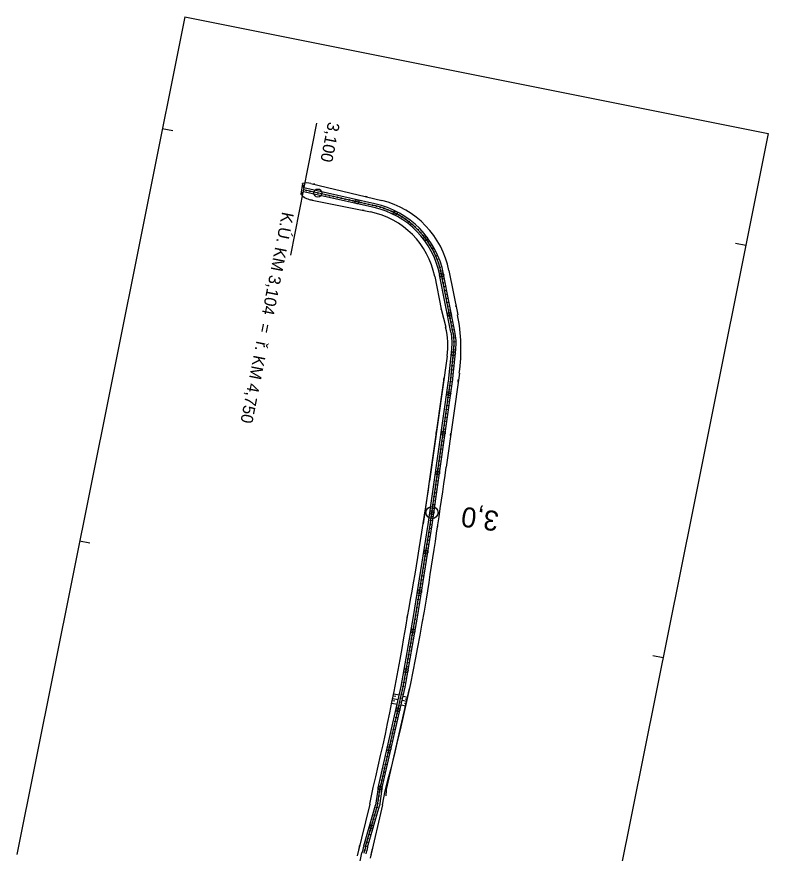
# Model space of a CAD drawing. Extents: x -548552 to -543113, y -1131925 to -1123599.
# Drawn here: x -548501.2 to -548313.7, y -1124330.1 to -1124121.2 of the extents above; entities that cross this region are included whole.
import ezdxf

# ---------------------------------------------------------------- set-up
doc = ezdxf.new("R2010")
doc.units = 0
for name, color, linetype in [('HRANY', 7, 'Continuous'), ('Profile', 7, 'Continuous'), ('PROFILY NÁVRH', 7, 'Continuous'), ('STANIČENÍ', 7, 'Continuous'), ('SVAHY', 7, 'Continuous')]:
    doc.layers.add(name, color=color, linetype=linetype)

msp = doc.modelspace()

# ---------------------------------------------------------------- linework, layer by layer
at = {"layer": 'HRANY'}
for p, q in [((-548394.66, -1124211.53), (-548399.79, -1124247.8)), ((-548413.11, -1124317.81), (-548412.26, -1124313.64)), ((-548409.92, -1124318), (-548409.29, -1124314.45))]:
    msp.add_line(p, q, dxfattribs=at)
msp.add_lwpolyline([(-548409.01, -1124315.73), (-548408.93, -1124314.27), (-548408.93, -1124314.11), (-548403.18, -1124288.88)], dxfattribs=at)
at = {"layer": 'Profile'}
for p, q in [((-548459.29, -1124121.17), (-548478.12, -1124215.1)), ((-548459.29, -1124121.17), (-548313.69, -1124150.35)), ((-548462.31, -1124149.67), (-548464.9, -1124149.15)), ((-548313.69, -1124150.35), (-548332.52, -1124244.29)), ((-548319.3, -1124178.33), (-548321.89, -1124177.81)), ((-548478.12, -1124215.1), (-548501.23, -1124330.39)), ((-548332.52, -1124244.29), (-548355.63, -1124359.57)), ((-548482.95, -1124252.62), (-548485.54, -1124252.1)), ((-548339.93, -1124281.29), (-548342.52, -1124280.77))]:
    msp.add_line(p, q, dxfattribs=at)
at = {"layer": 'PROFILY NÁVRH'}
for p, q in [((-548429.93, -1124162.84), (-548430.3, -1124165.5)), ((-548429.56, -1124163.91), (-548429.93, -1124162.84)), ((-548427.8, -1124162.78), (-548410.15, -1124167.05)), ((-548426.87, -1124163), (-548427.15, -1124162.94)), ((-548429.67, -1124164.91), (-548430.3, -1124165.5)), ((-548412.06, -1124168.83), (-548429.67, -1124164.91)), ((-548411.95, -1124168.35), (-548429.62, -1124164.41)), ((-548411.84, -1124167.86), (-548429.56, -1124163.91)), ((-548427.94, -1124166.87), (-548412.97, -1124169.91)), ((-548427.42, -1124166.98), (-548427.85, -1124166.88)), ((-548413.81, -1124166.16), (-548414.22, -1124166.07)), ((-548414.55, -1124169.59), (-548414.96, -1124169.5)), ((-548396.91, -1124186.06), (-548395.31, -1124194.21)), ((-548392.86, -1124199.93), (-548395.69, -1124185.62)), ((-548391.88, -1124199.74), (-548394.71, -1124185.42)), ((-548393.37, -1124184.56), (-548391.19, -1124195.59)), ((-548395.31, -1124194.21), (-548394.19, -1124198.68)), ((-548393.39, -1124211.43), (-548392.66, -1124204.2)), ((-548392.39, -1124211.53), (-548391.67, -1124204.29)), ((-548393.82, -1124205.97), (-548398.22, -1124237.17)), ((-548390.78, -1124210.15), (-548394.06, -1124233.66)), ((-548398.53, -1124247.94), (-548393.46, -1124212.09)), ((-548397.54, -1124248.09), (-548392.47, -1124212.23)), ((-548402.21, -1124270.91), (-548398.53, -1124247.94)), ((-548401.23, -1124271.07), (-548397.54, -1124248.09)), ((-548396.23, -1124248.66), (-548396.18, -1124248.35)), ((-548405.29, -1124288.38), (-548402.21, -1124270.91)), ((-548404.31, -1124288.58), (-548401.23, -1124271.07)), ((-548411.06, -1124313.75), (-548405.29, -1124288.38)), ((-548410.08, -1124313.97), (-548404.31, -1124288.58)), ((-548411.06, -1124313.75), (-548411.73, -1124318.04)), ((-548410.08, -1124313.97), (-548410.72, -1124318.18)), ((-548413.11, -1124317.81), (-548416.3, -1124330.72)), ((-548414.64, -1124328.25), (-548411.73, -1124318.04)), ((-548413.68, -1124328.52), (-548410.72, -1124318.18)), ((-548409.92, -1124318), (-548413.06, -1124331.3)), ((-548421.59, -1124360.69), (-548415.07, -1124329.96))]:
    msp.add_line(p, q, dxfattribs=at)
for centre, radius, start, end in [((-548428.76, -1124166.75), 4.08, 76.4037, 106.7435), ((-548427.09, -1124162.67), 4.28, 221.3954, 258.5091), ((-548415.43, -1124188.91), 22.49, 11.1558, 76.4037), ((-548417.07, -1124190.04), 20.54, 11.1558, 78.5091), ((-548434.29, -1124204.08), 43.92, 352.057, 11.1558), ((-548412.74, -1124203.3), 19.11, 351.9688, 13.9759), ((-549961.12, -1124015.02), 1582.24, 350.85166, 352.05699), ((-549178.83, -1124127.03), 788.35, 349.48348, 351.9688), ((-548865.33, -1124191.48), 472.33, 344.9096, 350.8517), ((-548972.72, -1124179.46), 576.3, 346.53607, 350.86921)]:
    msp.add_arc(centre, radius, start, end, dxfattribs=at)
for centre, major_axis, ratio, start_param, end_param in [((-548416.73, -1124189.76), (20.15, 7.35), 0.999974, 6.128055, 7.284874), ((-548416.73, -1124189.76), (21.08, 7.69), 0.999975, 6.128055, 7.284874), ((-548407.05, -1124202.74), (-1.33, 14.44), 0.997522, 4.519884, 4.815157), ((-548407.05, -1124202.74), (-1.43, 15.43), 0.997682, 4.519884, 4.815157), ((-548406.13, -1124210.24), (1.81, 14.39), 0.88281, 4.695435, 4.741018), ((-548406.13, -1124210.24), (1.94, 15.38), 0.890371, 4.695435, 4.741018), ((-548390.14, -1124335.25), (-10.13, -23.4), 0.999371, 4.842823, 4.912092), ((-548390.14, -1124335.25), (-9.74, -22.48), 0.999345, 4.842826, 4.912097)]:
    msp.add_ellipse(centre, major_axis=major_axis, ratio=ratio, start_param=start_param, end_param=end_param, dxfattribs=at)
at = {"layer": 'STANIČENÍ'}
for p, q in [((-548432.86, -1124180.71), (-548426.31, -1124147.71)), ((-548392.37, -1124199.84), (-548395.2, -1124185.52)), ((-548395.29, -1124194.3), (-548395.33, -1124194.1)), ((-548391.59, -1124193.58), (-548391.63, -1124193.39)), ((-548392.89, -1124211.48), (-548392.16, -1124204.24)), ((-548398.03, -1124248.01), (-548392.97, -1124212.16)), ((-548396.54, -1124225.25), (-548396.45, -1124224.61)), ((-548392.96, -1124225.76), (-548392.87, -1124225.14)), ((-548401.72, -1124270.99), (-548398.03, -1124248.01)), ((-548399.79, -1124247.77), (-548399.74, -1124247.43)), ((-548404.8, -1124288.48), (-548401.72, -1124270.99)), ((-548403.78, -1124271.21), (-548403.68, -1124270.65)), ((-548399.89, -1124271.96), (-548399.78, -1124271.33)), ((-548410.57, -1124313.86), (-548404.8, -1124288.48)), ((-548406.9, -1124288.78), (-548406.77, -1124288.24)), ((-548403.3, -1124289.56), (-548403.2, -1124289.12)), ((-548410.85, -1124315.88), (-548410.57, -1124313.86)), ((-548411.23, -1124318.12), (-548410.85, -1124315.88)), ((-548414.16, -1124328.39), (-548411.23, -1124318.12))]:
    msp.add_line(p, q, dxfattribs=at)
for centre, radius in [((-548428.93, -1124164.56), 0.1), ((-548428, -1124164.77), 0.1), ((-548427.07, -1124164.98), 0.1), ((-548426.09, -1124165.19), 1), ((-548426.1, -1124165.19), 0.1), ((-548425.12, -1124165.41), 0.1), ((-548424.14, -1124165.63), 0.1), ((-548423.17, -1124165.84), 0.1), ((-548422.19, -1124166.06), 0.1), ((-548421.21, -1124166.28), 0.1), ((-548420.24, -1124166.49), 0.1), ((-548419.26, -1124166.71), 0.1), ((-548418.28, -1124166.92), 0.1), ((-548417.31, -1124167.14), 0.1), ((-548416.33, -1124167.36), 0.5), ((-548416.33, -1124167.36), 0.1), ((-548415.36, -1124167.57), 0.1), ((-548414.38, -1124167.79), 0.1), ((-548413.4, -1124168.01), 0.1), ((-548412.43, -1124168.22), 0.1), ((-548411.46, -1124168.46), 0.1), ((-548410.49, -1124168.72), 0.1), ((-548409.54, -1124169.03), 0.1), ((-548408.6, -1124169.38), 0.1), ((-548407.68, -1124169.77), 0.1), ((-548406.78, -1124170.2), 0.5), ((-548406.78, -1124170.2), 0.1), ((-548405.9, -1124170.68), 0.1), ((-548405.04, -1124171.19), 0.1), ((-548404.21, -1124171.74), 0.1), ((-548403.4, -1124172.33), 0.1), ((-548402.62, -1124172.96), 0.1), ((-548401.87, -1124173.62), 0.1), ((-548401.15, -1124174.31), 0.1), ((-548400.46, -1124175.03), 0.1), ((-548399.81, -1124175.79), 0.1), ((-548399.19, -1124176.58), 0.5), ((-548399.19, -1124176.58), 0.1), ((-548398.6, -1124177.39), 0.1), ((-548398.06, -1124178.23), 0.1), ((-548397.55, -1124179.09), 0.1), ((-548397.09, -1124179.97), 0.1), ((-548396.66, -1124180.88), 0.1), ((-548396.28, -1124181.8), 0.1), ((-548395.94, -1124182.74), 0.1), ((-548395.64, -1124183.7), 0.1), ((-548395.17, -1124185.64), 0.5), ((-548395.38, -1124184.66), 0.1), ((-548395.17, -1124185.64), 0.1), ((-548394.98, -1124186.62), 0.1), ((-548394.79, -1124187.6), 0.1), ((-548394.59, -1124188.58), 0.1), ((-548394.4, -1124189.56), 0.1), ((-548394.2, -1124190.55), 0.1), ((-548394.01, -1124191.53), 0.1), ((-548393.82, -1124192.51), 0.1), ((-548393.62, -1124193.49), 0.1), ((-548393.43, -1124194.47), 0.1), ((-548393.24, -1124195.45), 0.5), ((-548393.24, -1124195.45), 0.1), ((-548393.04, -1124196.43), 0.1), ((-548392.85, -1124197.41), 0.1), ((-548392.66, -1124198.39), 0.1), ((-548392.46, -1124199.38), 0.1), ((-548392.28, -1124200.36), 0.1), ((-548392.15, -1124201.35), 0.1), ((-548392.09, -1124202.35), 0.1), ((-548392.27, -1124205.34), 0.5), ((-548392.17, -1124204.34), 0.1), ((-548392.1, -1124203.35), 0.1), ((-548392.37, -1124206.33), 0.1), ((-548392.27, -1124205.34), 0.1), ((-548392.67, -1124209.32), 0.1), ((-548392.57, -1124208.32), 0.1), ((-548392.47, -1124207.33), 0.1), ((-548392.87, -1124211.31), 0.1), ((-548392.77, -1124210.31), 0.1), ((-548393.13, -1124213.29), 0.1), ((-548392.99, -1124212.3), 0.1), ((-548393.41, -1124215.27), 0.5), ((-548393.41, -1124215.27), 0.1), ((-548393.27, -1124214.28), 0.1), ((-548393.69, -1124217.25), 0.1), ((-548393.55, -1124216.26), 0.1), ((-548393.97, -1124219.23), 0.1), ((-548393.83, -1124218.24), 0.1), ((-548394.25, -1124221.21), 0.1), ((-548394.11, -1124220.22), 0.1), ((-548394.53, -1124223.19), 0.1), ((-548394.39, -1124222.2), 0.1), ((-548394.81, -1124225.17), 0.5), ((-548394.81, -1124225.17), 0.1), ((-548394.67, -1124224.18), 0.1), ((-548395.09, -1124227.15), 0.1), ((-548394.95, -1124226.16), 0.1), ((-548395.51, -1124230.12), 0.1), ((-548395.37, -1124229.13), 0.1), ((-548395.23, -1124228.14), 0.1), ((-548395.79, -1124232.1), 0.1), ((-548395.65, -1124231.11), 0.1), ((-548396.07, -1124234.09), 0.1), ((-548395.93, -1124233.1), 0.1), ((-548396.21, -1124235.08), 0.5), ((-548396.35, -1124236.07), 0.1), ((-548396.21, -1124235.08), 0.1), ((-548396.63, -1124238.05), 0.1), ((-548396.49, -1124237.06), 0.1), ((-548396.91, -1124240.03), 0.1), ((-548396.77, -1124239.04), 0.1), ((-548397.19, -1124242.01), 0.1), ((-548397.05, -1124241.02), 0.1), ((-548397.6, -1124244.98), 1.5), ((-548397.6, -1124244.98), 0.5), ((-548397.47, -1124243.99), 0.1), ((-548397.33, -1124243), 0.1), ((-548397.74, -1124245.97), 0.1), ((-548397.6, -1124244.98), 0.1), ((-548398.18, -1124248.93), 0.1), ((-548398.02, -1124247.95), 0.1), ((-548397.88, -1124246.96), 0.1), ((-548398.5, -1124250.91), 0.1), ((-548398.34, -1124249.92), 0.1), ((-548398.82, -1124252.88), 0.1), ((-548398.66, -1124251.9), 0.1), ((-548399.13, -1124254.86), 0.5), ((-548399.13, -1124254.86), 0.1), ((-548398.97, -1124253.87), 0.1), ((-548399.45, -1124256.83), 0.1), ((-548399.29, -1124255.85), 0.1), ((-548399.77, -1124258.81), 0.1), ((-548399.61, -1124257.82), 0.1), ((-548400.08, -1124260.78), 0.1), ((-548399.92, -1124259.8), 0.1), ((-548400.4, -1124262.76), 0.1), ((-548400.24, -1124261.77), 0.1), ((-548400.72, -1124264.73), 0.5), ((-548400.87, -1124265.72), 0.1), ((-548400.72, -1124264.73), 0.1), ((-548400.56, -1124263.74), 0.1), ((-548401.19, -1124267.69), 0.1), ((-548401.03, -1124266.71), 0.1), ((-548401.51, -1124269.67), 0.1), ((-548401.35, -1124268.68), 0.1), ((-548401.84, -1124271.64), 0.1), ((-548401.67, -1124270.66), 0.1), ((-548402.18, -1124273.61), 0.1), ((-548402.01, -1124272.63), 0.1), ((-548402.36, -1124274.6), 0.5), ((-548402.53, -1124275.58), 0.1), ((-548402.36, -1124274.6), 0.1), ((-548402.88, -1124277.55), 0.1), ((-548402.7, -1124276.57), 0.1), ((-548403.22, -1124279.52), 0.1), ((-548403.05, -1124278.54), 0.1), ((-548403.57, -1124281.49), 0.1), ((-548403.39, -1124280.51), 0.1), ((-548404.09, -1124284.45), 0.5), ((-548404.09, -1124284.45), 0.1), ((-548403.91, -1124283.46), 0.1), ((-548403.74, -1124282.48), 0.1), ((-548404.43, -1124286.41), 0.1), ((-548404.26, -1124285.43), 0.1), ((-548404.78, -1124288.38), 0.1), ((-548404.61, -1124287.4), 0.1), ((-548405.22, -1124290.34), 0.1), ((-548405, -1124289.36), 0.1), ((-548405.66, -1124292.29), 0.1), ((-548405.44, -1124291.31), 0.1), ((-548406.11, -1124294.24), 0.5), ((-548406.11, -1124294.24), 0.1), ((-548405.88, -1124293.26), 0.1), ((-548406.55, -1124296.19), 0.1), ((-548406.33, -1124295.21), 0.1), ((-548407.21, -1124299.11), 0.1), ((-548406.99, -1124298.14), 0.1), ((-548406.77, -1124297.16), 0.1), ((-548407.66, -1124301.06), 0.1), ((-548407.44, -1124300.09), 0.1), ((-548408.1, -1124303.01), 0.1), ((-548407.88, -1124302.04), 0.1), ((-548408.32, -1124303.99), 0.5), ((-548408.54, -1124304.96), 0.1), ((-548408.32, -1124303.99), 0.1), ((-548408.99, -1124306.91), 0.1), ((-548408.77, -1124305.94), 0.1), ((-548409.43, -1124308.86), 0.1), ((-548409.21, -1124307.89), 0.1), ((-548409.87, -1124310.81), 0.1), ((-548409.65, -1124309.84), 0.1), ((-548410.54, -1124313.74), 0.5), ((-548410.54, -1124313.74), 0.1), ((-548410.32, -1124312.76), 0.1), ((-548410.1, -1124311.79), 0.1), ((-548410.83, -1124315.72), 0.1), ((-548410.69, -1124314.73), 0.1), ((-548411.16, -1124317.69), 0.1), ((-548410.99, -1124316.7), 0.1), ((-548411.66, -1124319.62), 0.1), ((-548411.38, -1124318.66), 0.1), ((-548412.21, -1124321.55), 0.1), ((-548411.93, -1124320.58), 0.1), ((-548412.76, -1124323.47), 0.5), ((-548412.76, -1124323.47), 0.1), ((-548412.48, -1124322.51), 0.1), ((-548413.31, -1124325.39), 0.1), ((-548413.03, -1124324.43), 0.1), ((-548414.13, -1124328.28), 0.1), ((-548413.86, -1124327.32), 0.1), ((-548413.58, -1124326.35), 0.1), ((-548414.39, -1124329.24), 0.1)]:
    msp.add_circle(centre, radius, dxfattribs=at)
for centre, major_axis, ratio, start_param, end_param in [((-548416.73, -1124189.76), (20.62, 7.52), 0.999974, 6.128055, 7.284874), ((-548407.05, -1124202.74), (-1.38, 14.94), 0.997605, 4.519884, 4.815157), ((-548406.13, -1124210.24), (1.66, 13.2), 0.872237, 4.695435, 4.741018), ((-548406.13, -1124210.24), (1.87, 14.88), 0.886717, 4.695435, 4.741018), ((-548406.13, -1124210.24), (2.11, 16.76), 0.899393, 4.695435, 4.741018), ((-548390.14, -1124335.25), (-10.54, -24.33), 0.999395, 4.842824, 4.912095), ((-548390.14, -1124335.25), (-9.94, -22.94), 0.999358, 4.842824, 4.912095), ((-548390.14, -1124335.25), (-9.24, -21.33), 0.999309, 4.842824, 4.912095)]:
    msp.add_ellipse(centre, major_axis=major_axis, ratio=ratio, start_param=start_param, end_param=end_param, dxfattribs=at)
at = {"layer": 'SVAHY'}
for p, q in [((-548407.15, -1124290.22), (-548405.78, -1124290.53)), ((-548407.63, -1124292.56), (-548406.31, -1124292.86)), ((-548406.9, -1124292.09), (-548407.51, -1124291.97)), ((-548407.38, -1124291.38), (-548406.04, -1124291.68)), ((-548406.65, -1124290.92), (-548407.28, -1124290.8)), ((-548405.06, -1124291.85), (-548403.85, -1124292.12)), ((-548404.82, -1124290.8), (-548403.62, -1124291.05)), ((-548404.47, -1124292.59), (-548403.97, -1124292.7)), ((-548404.27, -1124291.46), (-548403.73, -1124291.58)), ((-548405.3, -1124293.01), (-548404.1, -1124293.28))]:
    msp.add_line(p, q, dxfattribs=at)

# ---------------------------------------------------------------- texts
at = {"layer": 'STANIČENÍ'}
for s, height, rotation, p in [('3,100', 3, 258.7662, (-548423.52, -1124147.3)), ('K.Ú. KM 3,104  =  ř. KM 4,750 ', 3, 258.7662, (-548434.98, -1124169.77)), ('3,0', 5, 171.9617, (-548380.68, -1124244.77))]:
    msp.add_text(s, height=height, rotation=rotation, dxfattribs=at).set_placement(p)

doc.saveas('drawing.dxf')
